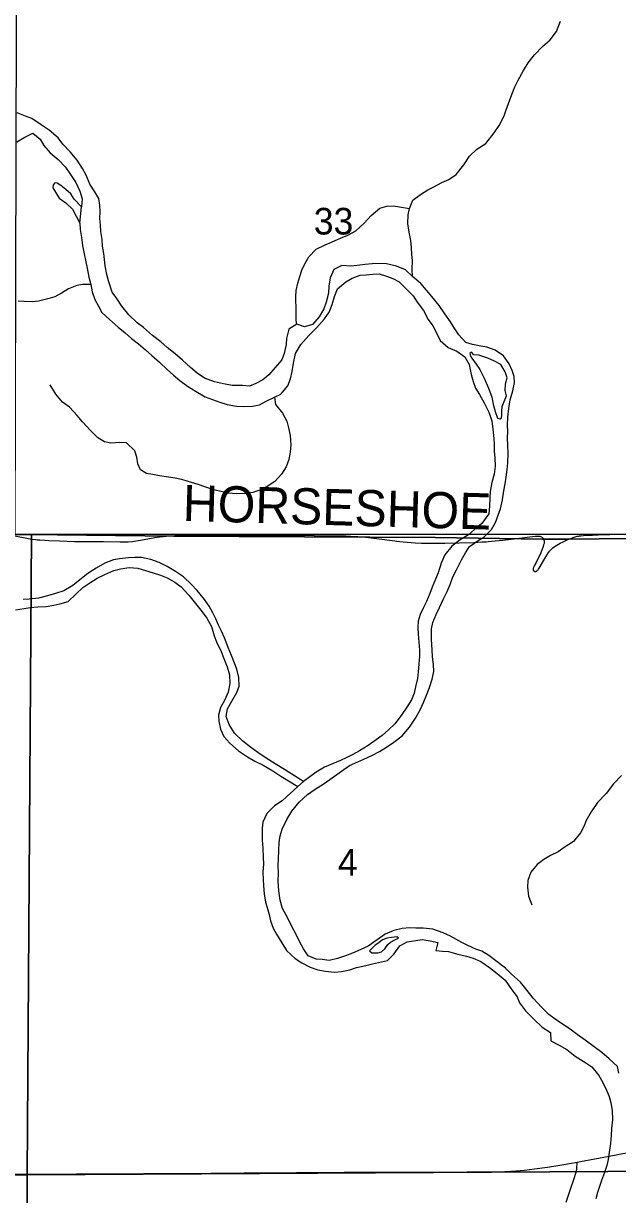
# Model space of a CAD drawing. Extents: x 0 to 680, y 0 to 440.
# Drawn here: x 365.58 to 382.07, y 276.66 to 309.11 of the extents above; entities that cross this region are included whole.
import ezdxf

# ---------------------------------------------------------------- set-up
doc = ezdxf.new("R2010")
doc.units = 0
for name, color, linetype in [('GM_X_County_Road', 7, 'Continuous'), ('GM_X_County_Road_Text', 7, 'Continuous'), ('GM_X_Major_River', 7, 'Continuous'), ('GM_X_Minor_River', 7, 'Continuous'), ('GM_X_Section', 7, 'Continuous'), ('GM_X_Section_Text', 7, 'Continuous'), ('GM_X_State_Route', 7, 'Continuous'), ('GM_X_Township', 7, 'Continuous'), ('GM_X_Township_Road', 7, 'Continuous')]:
    doc.layers.add(name, color=color, linetype=linetype)

msp = doc.modelspace()

# ---------------------------------------------------------------- linework, layer by layer
at = {"layer": 'GM_X_County_Road'}
for points in [[(380.687, 294.807), (380.743, 294.83), (380.794, 294.85), (380.832, 294.864), (380.865, 294.876), (380.888, 294.883), (380.92, 294.892), (380.947, 294.899), (380.982, 294.906), (381.012, 294.91), (381.043, 294.914), (381.124, 294.922), (381.251, 294.928), (381.372, 294.933), (381.524, 294.938), (383.457, 294.998), (386.255, 294.977), (386.977, 294.979), (387.753, 294.978), (391.88, 294.94)], [(365.295, 294.917), (365.629, 294.858), (365.822, 294.823), (365.916, 294.81), (365.968, 294.804), (366.044, 294.797), (366.182, 294.788), (366.285, 294.782), (366.582, 294.77), (366.999, 294.757), (367.273, 294.755), (367.806, 294.754), (368.268, 294.747), (368.488, 294.75), (368.607, 294.756), (368.659, 294.762), (368.777, 294.781), (369.032, 294.831), (369.225, 294.867), (369.366, 294.886), (369.465, 294.897), (369.627, 294.911), (369.945, 294.926), (370.382, 294.929), (370.917, 294.932), (371.903, 294.93)], [(371.903, 294.93), (372.016, 294.93), (372.436, 294.931), (372.8, 294.928)], [(372.8, 294.928), (372.93, 294.928)], [(372.93, 294.928), (373.647, 294.922), (374.436, 294.912), (374.526, 294.909), (374.785, 294.897), (374.861, 294.892), (375.077, 294.872), (375.161, 294.862), (375.375, 294.837), (375.888, 294.769), (375.947, 294.762), (376.03, 294.753), (376.115, 294.745), (376.448, 294.717), (376.627, 294.708), (376.698, 294.706), (376.852, 294.705), (377.278, 294.706), (378.075, 294.73), (378.3, 294.742), (378.417, 294.75), (378.48, 294.755)], [(378.48, 294.755), (378.568, 294.762), (378.883, 294.793), (379.275, 294.839), (379.784, 294.9), (379.811, 294.902), (379.859, 294.904), (379.887, 294.902), (379.912, 294.899), (379.932, 294.894)], [(379.932, 294.894), (379.953, 294.886), (379.968, 294.876), (379.983, 294.864), (379.995, 294.851), (380.004, 294.839), (380.013, 294.823), (380.021, 294.804), (380.024, 294.792), (380.028, 294.776), (380.029, 294.768), (380.03, 294.753), (380.03, 294.741), (380.03, 294.728), (380.029, 294.722), (380.027, 294.708), (380.026, 294.702), (380.021, 294.683), (380.014, 294.658), (380, 294.616), (379.933, 294.441), (379.878, 294.317), (379.839, 294.236), (379.796, 294.153), (379.754, 294.079), (379.74, 294.052), (379.734, 294.039), (379.726, 294.018), (379.722, 294.004), (379.72, 293.992), (379.721, 293.982), (379.721, 293.974), (379.722, 293.969), (379.724, 293.963), (379.728, 293.955), (379.731, 293.95), (379.734, 293.947), (379.738, 293.943), (379.743, 293.938), (379.748, 293.935), (379.755, 293.931), (379.76, 293.929), (379.769, 293.927), (379.777, 293.926), (379.784, 293.926), (379.79, 293.927), (379.794, 293.928), (379.798, 293.929), (379.804, 293.93), (379.807, 293.931), (379.814, 293.934), (379.819, 293.936), (379.824, 293.939), (379.833, 293.945), (379.839, 293.95), (379.848, 293.958), (379.86, 293.971), (379.871, 293.986), (379.89, 294.014), (380.079, 294.333), (380.123, 294.404), (380.133, 294.42), (380.177, 294.483), (380.201, 294.512), (380.219, 294.532), (380.251, 294.562), (380.274, 294.582), (380.303, 294.604), (380.379, 294.652), (380.43, 294.682), (380.477, 294.709), (380.556, 294.75), (380.591, 294.767), (380.632, 294.784), (380.687, 294.807)]]:
    msp.add_lwpolyline(points, dxfattribs=at)
at = {"layer": 'GM_X_Major_River'}
for p, q in [((367.151, 303.573), (367.192, 304.027)), ((373.352, 288.105), (373.192, 287.971))]:
    msp.add_line(p, q, dxfattribs=at)
for points in [[(373.166, 300.779), (372.949, 300.636), (372.878, 300.383), (372.869, 300.216), (372.818, 299.962), (372.755, 299.79), (372.57, 299.572), (372.393, 299.374), (372.223, 299.237), (372.034, 299.133), (371.853, 299.063), (371.659, 299.073), (371.378, 299.078), (371.131, 299.122), (370.884, 299.18), (370.605, 299.278), (370.407, 299.422), (370.222, 299.573), (369.998, 299.777), (369.793, 299.955), (369.575, 300.126), (369.397, 300.283), (369.166, 300.461), (368.916, 300.686), (368.744, 300.809), (368.507, 301.034), (368.317, 301.271), (368.173, 301.488), (368.049, 301.664), (367.947, 301.98), (367.896, 302.155), (367.854, 302.39), (367.836, 302.564), (367.812, 302.732), (367.782, 302.94), (367.765, 303.12), (367.736, 303.342), (367.719, 303.523), (367.708, 303.703), (367.711, 303.891), (367.708, 304.078), (367.677, 304.259), (367.567, 304.442), (367.43, 304.658), (367.327, 304.901), (367.223, 305.09), (367.073, 305.32), (366.883, 305.551), (366.679, 305.762), (366.548, 305.938), (366.297, 306.156), (366.079, 306.3), (365.814, 306.472), (365.641, 306.542), (365.415, 306.633)], [(365.402, 305.824), (365.625, 305.954), (365.841, 306.07), (366.046, 305.906), (366.15, 305.724), (366.327, 305.527), (366.545, 305.342), (366.755, 305.131), (366.892, 304.922), (367.042, 304.698), (367.145, 304.462), (367.216, 304.247), (367.192, 304.027)], [(367.192, 304.027), (366.995, 304.238), (366.897, 304.386), (366.758, 304.509), (366.62, 304.619), (366.52, 304.687), (366.453, 304.688), (366.406, 304.636), (366.398, 304.556), (366.574, 304.272), (366.759, 304.135), (366.943, 303.964), (367.151, 303.573)], [(367.151, 303.573), (367.161, 303.398), (367.191, 303.177), (367.227, 302.956), (367.27, 302.721), (367.314, 302.506), (367.351, 302.332), (367.4, 302.076), (367.457, 301.875), (367.494, 301.673), (367.564, 301.458), (367.668, 301.276), (367.758, 301.1), (367.969, 300.909), (368.213, 300.698), (368.405, 300.541), (368.583, 300.384), (368.774, 300.233), (368.972, 300.069), (369.144, 299.912), (369.355, 299.721), (369.572, 299.524), (369.743, 299.367), (369.921, 299.217), (370.133, 299.059), (370.378, 298.908), (370.63, 298.763), (370.829, 298.686), (371.029, 298.615), (371.235, 298.552), (371.495, 298.507), (371.696, 298.497), (371.937, 298.506), (372.132, 298.543), (372.314, 298.64), (372.55, 298.756), (372.725, 298.84), (372.923, 299.071), (372.993, 299.264), (373.037, 299.464), (373.074, 299.697), (373.132, 299.964), (373.284, 300.215), (373.502, 300.459), (373.726, 300.683), (373.938, 300.92), (374.068, 301.105), (374.152, 301.317), (374.209, 301.544), (374.3, 301.756), (374.524, 301.946), (374.706, 302.05), (374.922, 302.133), (375.089, 302.144), (375.277, 302.161), (375.457, 302.171), (375.657, 302.107), (375.83, 302.044), (376.009, 301.954), (376.233, 301.729), (376.397, 301.559), (376.508, 301.383), (376.685, 301.152), (376.808, 300.903), (376.945, 300.726), (377.036, 300.558), (377.146, 300.328), (377.364, 300.13), (377.61, 300.032), (377.828, 299.868), (377.951, 299.658), (378.007, 299.383), (378.057, 299.188), (378.128, 299.006), (378.232, 298.83), (378.362, 298.601), (378.498, 298.337), (378.574, 298.095), (378.61, 297.867), (378.633, 297.612), (378.644, 297.445), (378.647, 297.244), (378.664, 297.077), (378.667, 296.842), (378.643, 296.622), (378.579, 296.389), (378.535, 296.142), (378.518, 295.955), (378.515, 295.735), (378.498, 295.521), (378.299, 295.25), (378.096, 295.086), (377.926, 294.942), (377.696, 294.799), (377.472, 294.622), (377.274, 294.385), (377.17, 294.159), (377.085, 293.887), (377.015, 293.714), (376.925, 293.488), (376.855, 293.315)], [(372.708, 286.598), (372.758, 286.784), (372.89, 287.056), (373.027, 287.281), (373.232, 287.532), (373.463, 287.748), (373.653, 287.879), (373.923, 288.048), (374.153, 288.205), (374.411, 288.388), (374.627, 288.544), (374.857, 288.654), (375.025, 288.725), (375.248, 288.828), (375.464, 288.938), (375.66, 289.061), (375.863, 289.198), (376.093, 289.375), (376.291, 289.612), (376.462, 289.857), (376.594, 290.095), (376.684, 290.294), (376.768, 290.494), (376.845, 290.706), (376.922, 290.939), (376.973, 291.152), (376.962, 291.347), (376.933, 291.561), (376.922, 291.755), (376.907, 292.037), (376.905, 292.338), (376.942, 292.511), (377.032, 292.73), (377.123, 292.929), (377.24, 293.168), (377.338, 293.374), (377.421, 293.56), (377.498, 293.772), (377.595, 293.971), (377.734, 294.243), (377.851, 294.442), (377.96, 294.614), (378.198, 294.784), (378.367, 294.888), (378.564, 295.085), (378.681, 295.283), (378.758, 295.483), (378.814, 295.662), (378.872, 295.909), (378.91, 296.156), (378.946, 296.349), (378.976, 296.536), (379.007, 296.749), (379.023, 296.93), (379.027, 297.191), (379.024, 297.418), (379.015, 297.626), (379.018, 297.806), (379.014, 297.974), (379.017, 298.201), (379.048, 298.441), (379.086, 298.681), (379.164, 298.934), (379.207, 299.161), (379.197, 299.328), (379.146, 299.497), (379.062, 299.679), (378.899, 299.902), (378.674, 300.054), (378.441, 300.138), (378.268, 300.168), (378.041, 300.212), (377.854, 300.269), (377.664, 300.48), (377.553, 300.649), (377.429, 300.838), (377.272, 301.062), (377.115, 301.292), (376.912, 301.543), (376.768, 301.72), (376.604, 301.903), (376.38, 302.094), (376.182, 302.279), (375.936, 302.383), (375.656, 302.448), (375.442, 302.459), (375.261, 302.449), (375.06, 302.432), (374.839, 302.402), (374.665, 302.385), (374.418, 302.403), (374.195, 302.287), (374.091, 302.061), (374.06, 301.827), (374.043, 301.64), (373.986, 301.387), (373.922, 301.201), (373.792, 300.982), (373.601, 300.765), (373.379, 300.702), (373.166, 300.779)], [(378.01, 299.998), (377.97, 299.966), (377.995, 299.872), (378.021, 299.831), (378.139, 299.668), (378.243, 299.519), (378.366, 299.276), (378.489, 299.006), (378.578, 298.751), (378.615, 298.563), (378.666, 298.361)], [(378.666, 298.361), (378.736, 298.173), (378.803, 298.151), (378.809, 298.151), (378.843, 298.184), (378.858, 298.244), (378.853, 298.358), (378.869, 298.498), (378.924, 298.637), (378.98, 298.79), (378.95, 298.938), (378.959, 299.125), (379.002, 299.292), (378.945, 299.453), (378.828, 299.656), (378.649, 299.753), (378.463, 299.837), (378.216, 299.914), (378.083, 299.924), (378.01, 299.998)], [(376.855, 293.315), (376.764, 293.096), (376.681, 292.924), (376.591, 292.731), (376.534, 292.552), (376.525, 292.378), (376.535, 292.19), (376.551, 291.963), (376.574, 291.748), (376.572, 291.581), (376.554, 291.354), (376.538, 291.147), (376.514, 290.96), (376.464, 290.726), (376.421, 290.553), (376.351, 290.367), (376.22, 290.162), (376.062, 289.937), (375.884, 289.7), (375.708, 289.536), (375.538, 289.378), (375.369, 289.261), (375.145, 289.104), (374.908, 288.954), (374.726, 288.85), (374.551, 288.773), (374.382, 288.689), (374.16, 288.593), (373.937, 288.503), (373.708, 288.36), (373.352, 288.105)], [(373.192, 287.971), (372.764, 287.573), (372.548, 287.43), (372.337, 287.219), (372.226, 286.981), (372.21, 286.814), (372.207, 286.646), (372.211, 286.479), (372.227, 286.258), (372.236, 285.997), (372.24, 285.823), (372.229, 285.596), (372.233, 285.388), (372.243, 285.221), (372.266, 284.986), (372.303, 284.771)], [(372.768, 284.589), (372.705, 284.818), (372.669, 285.073), (372.653, 285.341), (372.657, 285.568), (372.654, 285.769), (372.657, 285.969), (372.678, 286.411), (372.708, 286.598)], [(372.303, 284.771), (372.397, 284.416), (372.44, 284.241), (372.516, 284.044), (372.606, 283.875), (372.754, 283.636), (372.883, 283.419), (373.126, 283.198), (373.311, 283.08), (373.536, 282.961), (373.749, 282.888), (373.963, 282.85), (374.211, 282.824), (374.406, 282.839), (374.635, 282.887), (374.825, 282.95), (375.081, 283.004), (375.263, 283.053), (375.432, 283.089), (375.682, 283.144), (375.86, 283.32), (376.027, 283.551), (376.231, 283.66), (376.474, 283.701), (376.649, 283.724), (376.869, 283.692), (377.083, 283.64), (377.024, 283.426), (377.205, 283.402), (377.379, 283.391), (377.639, 283.324), (377.879, 283.265), (378.059, 283.214), (378.272, 283.121), (378.509, 282.948), (378.727, 282.788), (378.95, 282.602), (379.132, 282.336), (379.281, 282.138), (379.344, 281.969), (379.513, 281.75), (379.743, 281.517), (379.972, 281.296), (380.203, 281.15), (380.218, 280.922), (380.45, 280.802), (380.655, 280.676), (380.885, 280.496), (381.183, 280.315), (381.355, 280.197), (381.55, 279.957), (381.653, 279.767), (381.762, 279.55), (381.831, 279.374), (381.881, 279.198), (381.916, 278.989), (381.923, 278.741), (381.897, 278.494), (381.886, 278.299), (381.867, 278.079), (381.834, 277.825), (381.802, 277.631), (381.772, 277.464), (381.7, 277.271), (381.621, 277.052), (381.505, 276.72), (381.461, 276.546)], [(382.1, 280.023), (382.063, 280.205), (381.831, 280.423), (381.625, 280.593), (381.412, 280.75), (381.167, 280.935), (380.947, 281.092), (380.748, 281.242), (380.562, 281.359), (380.336, 281.523), (380.156, 281.646), (379.951, 281.85), (379.726, 282.102), (379.562, 282.318), (379.37, 282.542), (379.125, 282.767), (378.953, 282.937), (378.687, 283.135), (378.495, 283.285), (378.302, 283.402), (378.135, 283.464), (377.915, 283.561), (377.741, 283.644), (377.428, 283.816), (377.228, 283.913), (376.941, 284.011), (376.673, 284.041), (376.471, 284.038), (376.304, 284.053), (376.089, 284.03), (375.86, 283.979), (375.617, 283.876), (375.393, 283.718), (375.149, 283.547), (374.94, 283.45), (374.71, 283.352), (374.521, 283.275), (374.292, 283.198), (374.063, 283.147), (373.868, 283.17), (373.701, 283.186), (373.481, 283.276), (373.349, 283.465), (373.245, 283.675), (373.153, 283.864), (373.029, 284.086), (372.931, 284.302), (372.768, 284.589)], [(375.879, 283.789), (375.791, 283.785), (375.677, 283.767), (375.548, 283.717), (375.445, 283.639), (375.343, 283.568), (375.254, 283.483), (375.185, 283.41), (375.251, 283.355), (375.412, 283.358), (375.513, 283.389), (375.609, 283.467), (375.692, 283.586), (375.768, 283.658)], [(375.768, 283.658), (375.883, 283.715), (375.992, 283.76), (375.946, 283.804), (375.879, 283.789)]]:
    msp.add_lwpolyline(points, dxfattribs=at)
at = {"layer": 'GM_X_Minor_River'}
msp.add_line((373.192, 287.971), (373.352, 288.105), dxfattribs=at)
for points in [[(376.38, 302.094), (376.37, 302.302), (376.374, 302.536), (376.363, 302.71), (376.353, 302.898), (376.329, 303.099), (376.28, 303.327), (376.244, 303.562), (376.261, 303.802), (376.297, 303.982), (376.388, 304.208), (376.598, 304.372), (376.801, 304.495), (376.97, 304.586), (377.193, 304.703), (377.388, 304.786), (377.591, 304.923), (377.803, 305.187), (377.954, 305.432), (378.165, 305.629), (378.408, 305.778), (378.647, 306.075), (378.778, 306.28), (378.916, 306.545), (378.973, 306.718), (379.042, 306.891), (379.134, 307.144), (379.217, 307.349), (379.307, 307.535), (379.459, 307.807), (379.583, 308.019), (379.761, 308.243), (379.985, 308.466), (380.196, 308.657), (380.367, 308.888), (380.486, 309.173)], [(373.166, 300.779), (373.148, 300.88), (373.152, 301.147), (373.145, 301.536), (373.148, 301.709), (373.192, 301.916), (373.248, 302.096), (373.311, 302.269), (373.395, 302.448), (373.498, 302.64), (373.709, 302.857), (373.952, 302.973), (374.127, 303.044), (374.397, 303.166), (374.565, 303.237), (374.808, 303.366), (375.039, 303.576), (375.23, 303.787), (375.474, 303.99), (375.663, 304.047), (375.85, 304.051), (376.297, 303.982)], [(367.457, 301.875), (367.236, 301.872), (367.068, 301.848), (366.839, 301.758), (366.637, 301.635), (366.454, 301.537), (366.266, 301.48), (366.004, 301.418), (365.836, 301.394), (365.609, 301.405), (365.442, 301.414)], [(372.55, 298.756), (372.58, 298.555), (372.77, 298.311), (372.887, 298.088), (372.937, 297.907), (372.987, 297.692), (373.003, 297.437), (372.986, 297.23), (372.949, 297.023), (372.872, 296.824), (372.742, 296.625), (372.558, 296.421), (372.348, 296.278), (372.146, 296.181), (371.951, 296.117), (371.743, 296.088), (371.502, 296.078), (371.268, 296.096), (371.094, 296.132), (370.868, 296.19), (370.615, 296.268), (370.435, 296.331), (370.249, 296.388), (370.009, 296.459), (369.796, 296.509), (369.609, 296.539), (369.362, 296.577), (369.175, 296.607), (369.002, 296.643), (368.83, 296.74), (368.759, 296.908), (368.728, 297.09), (368.678, 297.271), (368.447, 297.489), (368.26, 297.499), (368.012, 297.477), (367.832, 297.52), (367.647, 297.623), (367.443, 297.828), (367.226, 298.072), (367.075, 298.249), (366.858, 298.473), (366.666, 298.617), (366.483, 298.834), (366.326, 299.098)], [(373.352, 288.105), (373.031, 288.305), (372.826, 288.435), (372.567, 288.594), (372.316, 288.752), (372.084, 288.91), (371.886, 289.06), (371.675, 289.225), (371.444, 289.443), (371.288, 289.686), (371.211, 289.902), (371.248, 290.122), (371.365, 290.334), (371.503, 290.572), (371.566, 290.745), (371.564, 290.986), (371.501, 291.215), (371.436, 291.383), (371.353, 291.599), (371.263, 291.814), (371.16, 292.084), (371.076, 292.266), (370.992, 292.441), (370.922, 292.61), (370.838, 292.778), (370.734, 292.967), (370.61, 293.15), (370.4, 293.395), (370.248, 293.565), (370.025, 293.776), (369.806, 293.92), (369.574, 294.065), (369.349, 294.175), (369.123, 294.26), (368.856, 294.311), (368.675, 294.314), (368.501, 294.304), (368.246, 294.275), (368.079, 294.244), (367.843, 294.155), (367.6, 294.018), (367.37, 293.868), (367.193, 293.731), (366.956, 293.534), (366.706, 293.391), (366.471, 293.315), (366.249, 293.252), (366, 293.189), (365.745, 293.16), (365.578, 293.15)], [(365.366, 292.866), (365.607, 292.902), (365.775, 292.926), (365.983, 292.942), (366.217, 292.958), (366.425, 292.995), (366.593, 293.025), (366.821, 293.088), (367.039, 293.292), (367.229, 293.476), (367.399, 293.594), (367.629, 293.737), (367.844, 293.84), (368.094, 293.95), (368.275, 294), (368.517, 294.036), (368.757, 294.012), (368.97, 293.955), (369.183, 293.884), (369.39, 293.82), (369.569, 293.75), (369.788, 293.626), (369.96, 293.496), (370.17, 293.272), (370.36, 293.041), (370.544, 292.81), (370.668, 292.634), (370.798, 292.404), (370.874, 292.142), (370.944, 291.974), (371.067, 291.711), (371.144, 291.515), (371.234, 291.286), (371.297, 291.064), (371.313, 290.823), (371.262, 290.577), (371.158, 290.351), (371.054, 290.152), (370.998, 289.946), (371.001, 289.778), (371.051, 289.557), (371.148, 289.354), (371.306, 289.164), (371.55, 288.959), (371.801, 288.788), (372.007, 288.67), (372.232, 288.559), (372.504, 288.401), (372.729, 288.256), (373.192, 287.971)], [(382.177, 288.276), (381.952, 288.039), (381.747, 287.769), (381.508, 287.525), (381.33, 287.261), (381.199, 287.029), (381.129, 286.857), (381.039, 286.684), (380.841, 286.44), (380.584, 286.278), (380.415, 286.154), (380.206, 286.057), (380.017, 285.94), (379.834, 285.803), (379.663, 285.592), (379.579, 285.359), (379.569, 285.178), (379.592, 284.931), (379.688, 284.688)]]:
    msp.add_lwpolyline(points, dxfattribs=at)
at = {"layer": 'GM_X_Section'}
for points in [[(365.398, 312.641), (383.083, 312.727), (383.007, 294.958), (365.804, 294.95), (365.357, 294.952)], [(365.357, 294.952), (365.804, 294.95), (365.687, 277.203), (348.037, 276.897), (348.002, 295.007)], [(383.007, 294.958), (383.474, 294.949), (383.405, 277.313), (365.687, 277.203), (365.804, 294.95)], [(348.037, 276.897), (365.687, 277.203), (365.663, 259.44), (347.996, 259.569)], [(365.687, 277.203), (383.405, 277.313), (383.298, 259.399), (365.663, 259.44)]]:
    msp.add_lwpolyline(points, close=True, dxfattribs=at)
at = {"layer": 'GM_X_State_Route'}
msp.add_lwpolyline([(365.339, 277.226), (367.058, 277.235), (368.92, 277.247), (370.78, 277.257), (371.7, 277.262), (373.156, 277.273), (374.48, 277.277), (376.112, 277.283), (376.976, 277.285), (377.894, 277.293), (378.543, 277.293), (378.94, 277.302), (379.092, 277.308), (379.248, 277.316), (379.482, 277.338), (379.764, 277.372), (380.121, 277.423), (380.521, 277.487), (380.943, 277.56), (381.039, 277.576), (381.835, 277.725), (382.646, 277.878)], dxfattribs=at)
at = {"layer": 'GM_X_Township'}
for points in [[(345.039, 401.013), (345.039, 295.02), (350.497, 294.965), (353.224, 294.93), (357.228, 294.973), (360.054, 294.917), (364.9, 294.96), (369.752, 294.899), (377.006, 294.87), (379.986, 294.818), (380.635, 294.822), (391.775, 294.926), (392.287, 294.912), (400.568, 294.878), (400.602, 312.614), (400.766, 331.273), (400.686, 347.788), (400.683, 361.148)], [(418.103, 188.464), (418.29, 277.524), (418.638, 293.332), (418.665, 294.82), (409.368, 294.878), (405.452, 294.857), (392.287, 294.912), (391.775, 294.926), (380.635, 294.822), (379.986, 294.818), (377.006, 294.87), (369.752, 294.899), (364.9, 294.96), (360.054, 294.917), (357.228, 294.973), (353.224, 294.93), (350.497, 294.965), (345.039, 295.02), (345.039, 188.757)]]:
    msp.add_lwpolyline(points, dxfattribs=at)
at = {"layer": 'GM_X_Township_Road'}
msp.add_lwpolyline([(380.641, 276.453), (380.77, 276.838), (380.848, 277.081), (380.913, 277.285), (380.931, 277.356), (380.94, 277.424), (380.942, 277.508), (380.943, 277.56)], dxfattribs=at)

# ---------------------------------------------------------------- texts
at = {"layer": 'GM_X_County_Road_Text'}
msp.add_text('HORSESHOE', height=1.0014, rotation=358.3675, dxfattribs=at).set_placement((369.996, 295.327))
at = {"layer": 'GM_X_Section_Text'}
for s, height, p in [('33', 0.7377, (373.638, 303.261)), ('4', 0.738, (374.306, 285.496))]:
    msp.add_text(s, height=height, rotation=0, dxfattribs=at).set_placement(p)

doc.saveas('drawing.dxf')
